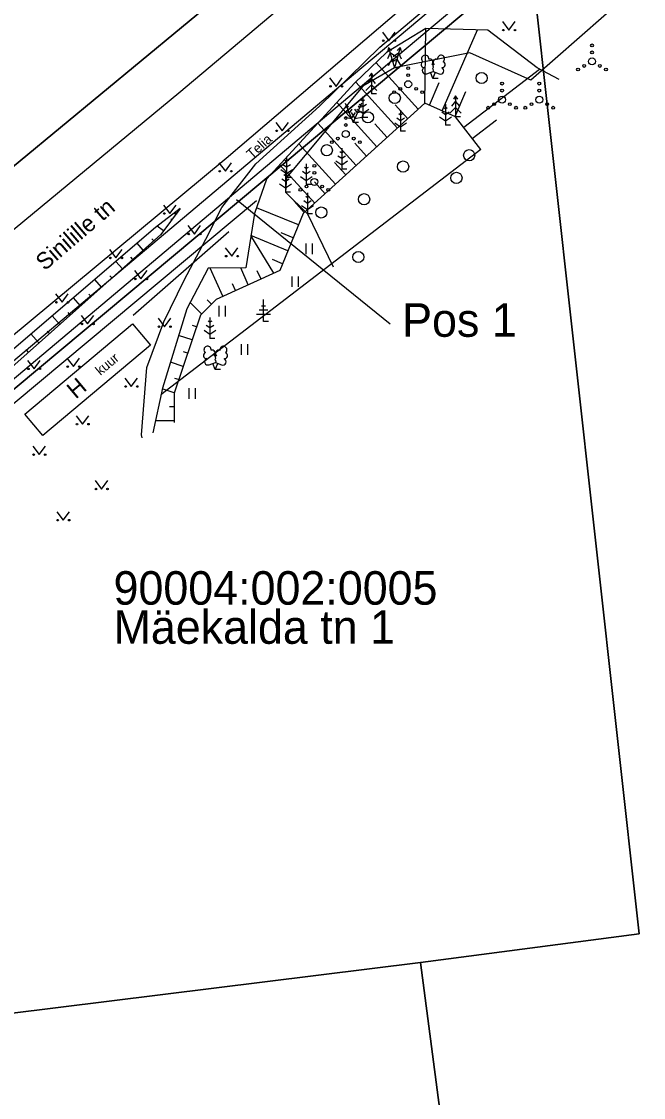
# Model space of a CAD drawing. Extents: x 648017 to 648227, y 6561313 to 6561610.
# Drawn here: x 648094.3 to 648138.8, y 6561381.6 to 6561458.6 of the extents above; entities that cross this region are included whole.
import ezdxf

# ---------------------------------------------------------------- set-up
doc = ezdxf.new("R2010")
doc.units = 0
for name, color, linetype in [('AED', 7, 'Continuous'), ('HALJASTUS', 7, 'Continuous'), ('HOONE', 7, 'Continuous'), ('KASUTUSALA', 7, 'Continuous'), ('PIIR', 7, 'Continuous'), ('PR_SIDE', 7, 'Continuous'), ('PUU', 7, 'Continuous'), ('RELJEEF', 7, 'Continuous'), ('SITRASS', 7, 'Continuous'), ('TEE', 7, 'Continuous'), ('VORMISTUS', 7, 'Continuous')]:
    doc.layers.add(name, color=color, linetype=linetype)

msp = doc.modelspace()

# ---------------------------------------------------------------- linework, layer by layer
at = {"layer": 'AED'}
msp.add_lwpolyline([(648111.122, 6561445.808), (648093.833, 6561431.357), (648080.35, 6561420.002), (648082.445, 6561407.838)], dxfattribs=at)
at = {"layer": 'HALJASTUS'}
for p, q in [((648128.734, 6561458.64), (648129.197, 6561458.033)), ((648129.197, 6561458.033), (648129.643, 6561458.64)), ((648120.134, 6561457.88), (648120.598, 6561457.274)), ((648120.598, 6561457.274), (648121.043, 6561457.88)), ((648116.354, 6561454.608), (648116.817, 6561454.001)), ((648116.817, 6561454.001), (648117.263, 6561454.608)), ((648112.504, 6561451.424), (648112.967, 6561450.818)), ((648112.967, 6561450.818), (648113.413, 6561451.424)), ((648108.424, 6561448.534), (648108.887, 6561447.928)), ((648108.887, 6561447.928), (648109.333, 6561448.534)), ((648104.45, 6561445.505), (648104.913, 6561444.899)), ((648104.913, 6561444.899), (648105.359, 6561445.505)), ((648102.276, 6561437.615), (648109.145, 6561443.615)), ((648106.203, 6561444.04), (648106.666, 6561443.433)), ((648106.666, 6561443.433), (648107.112, 6561444.04)), ((648114.639, 6561442.759), (648114.639, 6561441.998)), ((648115.094, 6561442.759), (648115.094, 6561441.998)), ((648100.589, 6561442.329), (648101.052, 6561441.722)), ((648101.052, 6561441.722), (648101.498, 6561442.329)), ((648108.88, 6561442.45), (648109.344, 6561441.844)), ((648109.344, 6561441.844), (648109.789, 6561442.45)), ((648102.377, 6561440.821), (648102.84, 6561440.214)), ((648102.84, 6561440.214), (648103.286, 6561440.821)), ((648113.649, 6561440.402), (648113.649, 6561439.641)), ((648114.104, 6561440.402), (648114.104, 6561439.641)), ((648096.727, 6561439.152), (648097.191, 6561438.545)), ((648097.191, 6561438.545), (648097.636, 6561439.152)), ((648108.423, 6561438.282), (648108.423, 6561437.521)), ((648108.878, 6561438.282), (648108.878, 6561437.521)), ((648098.551, 6561437.602), (648099.014, 6561436.995)), ((648099.014, 6561436.995), (648099.46, 6561437.602)), ((648104.07, 6561437.399), (648104.533, 6561436.792)), ((648104.533, 6561436.792), (648104.979, 6561437.399)), ((648110.027, 6561435.549), (648110.027, 6561434.788)), ((648110.482, 6561435.549), (648110.482, 6561434.788)), ((648094.725, 6561434.383), (648095.189, 6561433.776)), ((648095.189, 6561433.776), (648095.634, 6561434.383)), ((648097.537, 6561434.547), (648098, 6561433.94)), ((648098, 6561433.94), (648098.446, 6561434.547)), ((648101.683, 6561433.12), (648102.146, 6561432.513)), ((648102.146, 6561432.513), (648102.592, 6561433.12)), ((648106.265, 6561432.399), (648106.265, 6561431.638)), ((648106.72, 6561432.399), (648106.72, 6561431.638)), ((648098.193, 6561430.423), (648098.656, 6561429.816)), ((648098.656, 6561429.816), (648099.102, 6561430.423)), ((648095.088, 6561428.244), (648095.552, 6561427.637)), ((648095.552, 6561427.637), (648095.997, 6561428.244)), ((648099.555, 6561425.778), (648100.019, 6561425.172)), ((648100.019, 6561425.172), (648100.464, 6561425.778)), ((648096.809, 6561423.55), (648097.273, 6561422.943)), ((648097.273, 6561422.943), (648097.718, 6561423.55))]:
    msp.add_line(p, q, dxfattribs=at)
msp.add_lwpolyline([(648185.624, 6561501.029), (648186.158, 6561502.545), (648178.048, 6561502.668), (648168.965, 6561497.048), (648166.518, 6561494.366), (648160.96, 6561490.067), (648158.695, 6561487.313), (648156.134, 6561485.11), (648153.031, 6561483.538), (648142.942, 6561474.365), (648140.838, 6561468.512), (648139.267, 6561465.252), (648137.737, 6561460.573), (648130.77, 6561454.441), (648126.403, 6561456.396), (648120.992, 6561455.337), (648118.741, 6561454.027), (648113.276, 6561447.469), (648113.195, 6561446.44), (648114.768, 6561444.874), (648116.607, 6561441.073)], dxfattribs=at)
for centre, radius in [((648128.796, 6561458.033), 0.055), ((648129.625, 6561458.033), 0.055), ((648120.197, 6561457.274), 0.055), ((648121.025, 6561457.274), 0.055), ((648135.147, 6561456.939), 0.1), ((648135.147, 6561456.439), 0.1), ((648135.147, 6561455.789), 0.25), ((648121.982, 6561455.31), 0.1), ((648121.982, 6561454.81), 0.1), ((648127.24, 6561454.601), 0.4), ((648134.147, 6561455.214), 0.1), ((648134.582, 6561455.464), 0.1), ((648135.712, 6561455.464), 0.1), ((648136.147, 6561455.214), 0.1), ((648121.982, 6561454.16), 0.25), ((648128.703, 6561454.201), 0.1), ((648131.371, 6561454.201), 0.1), ((648116.416, 6561454.001), 0.055), ((648117.245, 6561454.001), 0.055), ((648121.023, 6561453.174), 0.4), ((648120.982, 6561453.585), 0.1), ((648121.417, 6561453.835), 0.1), ((648122.547, 6561453.835), 0.1), ((648122.982, 6561453.585), 0.1), ((648128.703, 6561453.701), 0.1), ((648131.371, 6561453.701), 0.1), ((648128.138, 6561452.726), 0.1), ((648128.703, 6561453.051), 0.25), ((648129.268, 6561452.726), 0.1), ((648130.806, 6561452.726), 0.1), ((648131.371, 6561453.051), 0.25), ((648131.936, 6561452.726), 0.1), ((648117.513, 6561451.739), 0.1), ((648119.096, 6561451.786), 0.4), ((648127.703, 6561452.476), 0.1), ((648129.703, 6561452.476), 0.1), ((648130.371, 6561452.476), 0.1), ((648132.371, 6561452.476), 0.1), ((648117.513, 6561451.239), 0.1), ((648112.566, 6561450.818), 0.055), ((648113.395, 6561450.818), 0.055), ((648116.948, 6561450.264), 0.1), ((648117.513, 6561450.589), 0.25), ((648118.078, 6561450.264), 0.1), ((648116.154, 6561449.431), 0.4), ((648116.513, 6561450.014), 0.1), ((648118.513, 6561450.014), 0.1), ((648126.349, 6561449.074), 0.4), ((648108.486, 6561447.928), 0.055), ((648109.315, 6561447.928), 0.055), ((648115.261, 6561448.315), 0.1), ((648121.617, 6561448.262), 0.4), ((648115.261, 6561447.165), 0.25), ((648115.261, 6561447.815), 0.1), ((648125.438, 6561447.45), 0.4), ((648114.261, 6561446.59), 0.1), ((648114.696, 6561446.84), 0.1), ((648115.826, 6561446.84), 0.1), ((648116.261, 6561446.59), 0.1), ((648118.826, 6561445.924), 0.4), ((648104.512, 6561444.899), 0.055), ((648105.341, 6561444.899), 0.055), ((648115.758, 6561444.974), 0.4), ((648106.265, 6561443.433), 0.055), ((648107.094, 6561443.433), 0.055), ((648108.943, 6561441.844), 0.055), ((648109.771, 6561441.844), 0.055), ((648118.41, 6561441.784), 0.4), ((648100.651, 6561441.722), 0.055), ((648101.48, 6561441.722), 0.055), ((648102.439, 6561440.214), 0.055), ((648103.268, 6561440.214), 0.055), ((648096.79, 6561438.545), 0.055), ((648097.619, 6561438.545), 0.055), ((648098.613, 6561436.995), 0.055), ((648099.442, 6561436.995), 0.055), ((648104.132, 6561436.792), 0.055), ((648104.961, 6561436.792), 0.055), ((648094.788, 6561433.776), 0.055), ((648095.616, 6561433.776), 0.055), ((648097.599, 6561433.94), 0.055), ((648098.428, 6561433.94), 0.055), ((648101.745, 6561432.513), 0.055), ((648102.574, 6561432.513), 0.055), ((648098.255, 6561429.816), 0.055), ((648099.084, 6561429.816), 0.055), ((648095.151, 6561427.637), 0.055), ((648095.98, 6561427.637), 0.055), ((648099.618, 6561425.172), 0.055), ((648100.447, 6561425.172), 0.055), ((648096.872, 6561422.943), 0.055), ((648097.701, 6561422.943), 0.055)]:
    msp.add_circle(centre, radius, dxfattribs=at)
at = {"layer": 'HOONE'}
msp.add_lwpolyline([(648094.535, 6561430.53), (648102.242, 6561436.998), (648103.52, 6561435.476), (648095.813, 6561429.007)], close=True, dxfattribs=at)
at = {"layer": 'KASUTUSALA'}
msp.add_lwpolyline([(648069.33, 6561411.95), (648079.41, 6561420.36), (648130.76, 6561463.29), (648148.46, 6561478.24), (648152.687, 6561481.861), (648163.17, 6561490.84), (648165.149, 6561492.835), (648178.343, 6561506.54), (648179.793, 6561507.812), (648180.15, 6561508.27), (648181.07, 6561509.57), (648179.717, 6561510.405), (648176.961, 6561507.989), (648163.749, 6561494.265), (648163.1, 6561493.666), (648154.204, 6561485.901), (648141.111, 6561474.192), (648118.068, 6561454.823), (648078.72, 6561421.738), (648068.502, 6561412.945), (648066.261, 6561409.593)], close=True, dxfattribs=at)
at = {"layer": 'PIIR'}
for points in [[(648199.342, 6561559.885), (648199.07, 6561558.2), (648195.16, 6561543.45), (648190.37, 6561530.46), (648184.89, 6561519.28), (648179.37, 6561510.62), (648181.07, 6561509.57), (648180.15, 6561508.27), (648175.42, 6561502.2), (648170.88, 6561497.65), (648163.17, 6561490.84), (648148.46, 6561478.24), (648130.76, 6561463.29), (648079.41, 6561420.36), (648069.33, 6561411.95), (648039.275, 6561388.867)], [(648148.783, 6561559.885), (648090, 6561513.15), (648123.09, 6561472.56), (648039.275, 6561403.329)], [(648039.275, 6561403.329), (648123.09, 6561472.56), (648162.4, 6561506.57), (648170.84, 6561515.84), (648172.53, 6561514.72), (648177.65, 6561522.71), (648182.83, 6561533.2), (648187.47, 6561545.71), (648191.21, 6561559.62), (648191.239, 6561559.885)], [(648128.277, 6561349.885), (648122.86, 6561391.28), (648138.52, 6561393.32), (648130.76, 6561463.29), (648148.46, 6561478.24), (648163.17, 6561490.84), (648170.88, 6561497.65), (648175.42, 6561502.2), (648180.15, 6561508.27), (648181.07, 6561509.57), (648185.28, 6561507.91), (648190.43, 6561507.33), (648190.49, 6561494.61), (648191.59, 6561478.79), (648183.88, 6561478.99), (648183.75, 6561472.33), (648192.14, 6561472), (648192.72, 6561465.96), (648194.12, 6561456.75), (648195.36, 6561449.36), (648197.34, 6561442.54), (648200.74, 6561433.7), (648204.275, 6561426.345)], [(648090.928, 6561349.885), (648085.73, 6561386.66), (648122.86, 6561391.28), (648128.277, 6561349.885)]]:
    msp.add_lwpolyline(points, dxfattribs=at)
msp.add_lwpolyline([(648079.41, 6561420.36), (648130.76, 6561463.29), (648138.52, 6561393.32), (648122.86, 6561391.28), (648085.73, 6561386.66)], close=True, dxfattribs=at)
at = {"layer": 'PR_SIDE'}
msp.add_lwpolyline([(648199.292, 6561518.475), (648197.479, 6561519.53), (648193.724, 6561520.506), (648191.997, 6561519.841), (648177.652, 6561507.265), (648164.449, 6561493.55), (648163.768, 6561492.922), (648154.867, 6561485.151), (648141.766, 6561473.436), (648118.712, 6561454.058), (648079.383, 6561420.989), (648069.186, 6561412.213), (648060.526, 6561403.421), (648044.656, 6561390.621), (648039.275, 6561386.529)], dxfattribs=at)
at = {"layer": 'PUU'}
for p, q in [((648120.583, 6561456.781), (648120.507, 6561456.499)), ((648120.795, 6561456.581), (648120.583, 6561456.781)), ((648120.583, 6561456.781), (648120.992, 6561455.337)), ((648121.401, 6561456.781), (648120.992, 6561455.337)), ((648121.188, 6561456.581), (648121.401, 6561456.781)), ((648121.401, 6561456.781), (648121.477, 6561456.499)), ((648120.692, 6561456.396), (648120.499, 6561455.977)), ((648120.815, 6561455.963), (648120.539, 6561455.469)), ((648121.076, 6561456.141), (648120.692, 6561456.396)), ((648121.076, 6561455.817), (648120.815, 6561455.963)), ((648120.908, 6561456.141), (648121.292, 6561456.396)), ((648120.908, 6561455.817), (648121.169, 6561455.963)), ((648121.169, 6561455.963), (648121.445, 6561455.469)), ((648121.292, 6561456.396), (648121.485, 6561455.977)), ((648119.346, 6561454.958), (648119.196, 6561454.708)), ((648119.496, 6561454.708), (648119.346, 6561454.958)), ((648119.346, 6561454.958), (648119.346, 6561453.458)), ((648121.352, 6561455.337), (648120.992, 6561455.337)), ((648123.315, 6561454.905), (648123.76, 6561455.08)), ((648123.755, 6561454.57), (648123.58, 6561455.01)), ((648123.755, 6561454.57), (648123.935, 6561455.01)), ((648123.76, 6561455.08), (648124.2, 6561454.9)), ((648119.346, 6561454.558), (648119.046, 6561454.208)), ((648119.646, 6561454.208), (648119.346, 6561454.558)), ((648124.135, 6561454.57), (648123.755, 6561454.57)), ((648119.346, 6561454.108), (648118.946, 6561453.708)), ((648119.746, 6561453.708), (648119.346, 6561454.108)), ((648119.706, 6561453.458), (648119.346, 6561453.458)), ((648117.469, 6561452.805), (648118.052, 6561451.423)), ((648117.688, 6561452.608), (648117.605, 6561452.483)), ((648118.634, 6561452.805), (648118.052, 6561451.423)), ((648118.498, 6561452.483), (648118.416, 6561452.608)), ((648118.736, 6561452.536), (648118.469, 6561452.714)), ((648118.736, 6561452.936), (648118.611, 6561453.019)), ((648118.736, 6561453.286), (648118.736, 6561451.786)), ((648118.86, 6561453.019), (648118.736, 6561452.936)), ((648119.002, 6561452.714), (648118.736, 6561452.536)), ((648124.647, 6561452.724), (648124.647, 6561451.224)), ((648125.376, 6561452.934), (648125.076, 6561452.584)), ((648125.376, 6561453.334), (648125.226, 6561453.084)), ((648125.526, 6561453.084), (648125.376, 6561453.334)), ((648125.376, 6561453.334), (648125.376, 6561451.834)), ((648125.676, 6561452.584), (648125.376, 6561452.934)), ((648117.76, 6561452.114), (648117.446, 6561452.175)), ((648117.605, 6561452.483), (648117.458, 6561452.511)), ((648117.937, 6561452.382), (648117.76, 6561452.114)), ((648117.889, 6561452.131), (648118.171, 6561451.706)), ((648117.933, 6561451.706), (648118.214, 6561452.131)), ((648118.343, 6561452.114), (648118.166, 6561452.382)), ((648118.312, 6561452.375), (648118.736, 6561452.093)), ((648118.657, 6561452.175), (648118.343, 6561452.114)), ((648118.645, 6561452.511), (648118.498, 6561452.483)), ((648118.736, 6561452.093), (648119.16, 6561452.375)), ((648121.44, 6561451.943), (648121.315, 6561452.026)), ((648121.44, 6561452.293), (648121.44, 6561450.793)), ((648121.564, 6561452.026), (648121.44, 6561451.943)), ((648124.223, 6561451.814), (648124.647, 6561451.531)), ((648124.647, 6561451.974), (648124.381, 6561452.152)), ((648124.647, 6561452.374), (648124.523, 6561452.457)), ((648124.772, 6561452.457), (648124.647, 6561452.374)), ((648124.914, 6561452.152), (648124.647, 6561451.974)), ((648124.647, 6561451.531), (648125.072, 6561451.814)), ((648125.376, 6561452.484), (648124.976, 6561452.084)), ((648125.776, 6561452.084), (648125.376, 6561452.484)), ((648125.736, 6561451.834), (648125.376, 6561451.834)), ((648117.432, 6561451.802), (648117.933, 6561451.706)), ((648118.412, 6561451.423), (648118.052, 6561451.423)), ((648118.171, 6561451.706), (648118.671, 6561451.802)), ((648119.096, 6561451.786), (648118.736, 6561451.786)), ((648121.015, 6561451.382), (648121.44, 6561451.099)), ((648121.44, 6561451.543), (648121.173, 6561451.721)), ((648121.706, 6561451.721), (648121.44, 6561451.543)), ((648121.44, 6561451.099), (648121.864, 6561451.382)), ((648125.007, 6561451.224), (648124.647, 6561451.224)), ((648121.8, 6561450.793), (648121.44, 6561450.793)), ((648117.22, 6561449.583), (648117.22, 6561448.083)), ((648113.276, 6561448.969), (648113.276, 6561447.469)), ((648117.22, 6561448.833), (648116.953, 6561449.01)), ((648117.22, 6561449.233), (648117.095, 6561449.316)), ((648117.344, 6561449.316), (648117.22, 6561449.233)), ((648117.486, 6561449.01), (648117.22, 6561448.833)), ((648112.852, 6561448.059), (648113.276, 6561447.776)), ((648113.276, 6561448.219), (648113.009, 6561448.397)), ((648113.276, 6561448.619), (648113.152, 6561448.702)), ((648113.401, 6561448.702), (648113.276, 6561448.619)), ((648113.543, 6561448.397), (648113.276, 6561448.219)), ((648113.276, 6561447.776), (648113.7, 6561448.059)), ((648114.685, 6561448.119), (648114.56, 6561448.202)), ((648114.685, 6561448.469), (648114.685, 6561446.969)), ((648114.809, 6561448.202), (648114.685, 6561448.119)), ((648116.795, 6561448.672), (648117.22, 6561448.389)), ((648117.22, 6561448.389), (648117.644, 6561448.672)), ((648117.58, 6561448.083), (648117.22, 6561448.083)), ((648113.195, 6561447.19), (648112.929, 6561447.368)), ((648113.195, 6561447.59), (648113.071, 6561447.673)), ((648113.195, 6561447.94), (648113.195, 6561446.44)), ((648113.32, 6561447.673), (648113.195, 6561447.59)), ((648113.462, 6561447.368), (648113.195, 6561447.19)), ((648113.636, 6561447.469), (648113.276, 6561447.469)), ((648114.26, 6561447.559), (648114.685, 6561447.276)), ((648114.685, 6561447.719), (648114.418, 6561447.897)), ((648114.951, 6561447.897), (648114.685, 6561447.719)), ((648114.685, 6561447.276), (648115.109, 6561447.559)), ((648112.771, 6561447.029), (648113.195, 6561446.747)), ((648113.195, 6561446.747), (648113.62, 6561447.029)), ((648113.555, 6561446.44), (648113.195, 6561446.44)), ((648115.045, 6561446.969), (648114.685, 6561446.969)), ((648114.768, 6561445.624), (648114.501, 6561445.801)), ((648114.768, 6561446.024), (648114.643, 6561446.107)), ((648114.768, 6561446.374), (648114.768, 6561444.874)), ((648114.892, 6561446.107), (648114.768, 6561446.024)), ((648115.034, 6561445.801), (648114.768, 6561445.624)), ((648114.343, 6561445.463), (648114.768, 6561445.18)), ((648114.768, 6561445.18), (648115.192, 6561445.463)), ((648115.128, 6561444.874), (648114.768, 6561444.874)), ((648111.62, 6561437.172), (648111.62, 6561438.747)), ((648111.92, 6561437.972), (648111.32, 6561437.972)), ((648111.77, 6561438.272), (648111.47, 6561438.272)), ((648107.783, 6561437.112), (648107.659, 6561437.195)), ((648107.783, 6561437.462), (648107.783, 6561435.962)), ((648107.908, 6561437.195), (648107.783, 6561437.112)), ((648112.12, 6561437.672), (648111.12, 6561437.672)), ((648111.98, 6561437.172), (648111.62, 6561437.172)), ((648107.359, 6561436.552), (648107.783, 6561436.269)), ((648107.783, 6561436.712), (648107.517, 6561436.89)), ((648108.05, 6561436.89), (648107.783, 6561436.712)), ((648107.783, 6561436.269), (648108.208, 6561436.552)), ((648108.143, 6561435.962), (648107.783, 6561435.962)), ((648107.729, 6561434.067), (648108.174, 6561434.242)), ((648108.169, 6561433.732), (648107.994, 6561434.173)), ((648108.169, 6561433.732), (648108.349, 6561434.173)), ((648108.174, 6561434.242), (648108.614, 6561434.062)), ((648108.549, 6561433.732), (648108.169, 6561433.732))]:
    msp.add_line(p, q, dxfattribs=at)
for points in [[(648123.76, 6561455.575), (648123.74, 6561455.5), (648123.74, 6561455.48), (648123.75, 6561455.45), (648123.77, 6561455.415), (648123.775, 6561455.395), (648123.76, 6561455.36), (648123.735, 6561455.31), (648123.73, 6561455.285), (648123.735, 6561455.27), (648123.745, 6561455.24), (648123.78, 6561455.18), (648123.785, 6561455.16), (648123.78, 6561455.14), (648123.765, 6561455.105), (648123.76, 6561455.08)], [(648108.174, 6561434.737), (648108.154, 6561434.663), (648108.154, 6561434.643), (648108.164, 6561434.612), (648108.184, 6561434.578), (648108.189, 6561434.558), (648108.174, 6561434.522), (648108.149, 6561434.473), (648108.144, 6561434.447), (648108.149, 6561434.433), (648108.159, 6561434.402), (648108.194, 6561434.343), (648108.199, 6561434.322), (648108.194, 6561434.303), (648108.179, 6561434.268), (648108.174, 6561434.242)]]:
    msp.add_lwpolyline(points, dxfattribs=at)
for centre, radius, start, end in [((648123.124, 6561455.573), 0.224, 111.43041, 274.49868), ((648123.198, 6561455.985), 0.256, 111.50269, 232.51731), ((648123.198, 6561455.985), 0.256, 350.48556, 111.50017), ((648123.532, 6561455.734), 0.224, 308.50412, 111.57247), ((648123.996, 6561455.729), 0.225, 67.7016, 230.51262), ((648124.334, 6561455.976), 0.256, 67.6168, 188.63142), ((648124.401, 6561455.563), 0.224, 264.6183, 67.68657), ((648124.334, 6561455.976), 0.256, 306.59966, 67.61428), ((648123.229, 6561455.129), 0.237, 111.50143, 291.50036), ((648123.759, 6561455.338), 0.237, 66.76552, 111.50149), ((648124.29, 6561455.121), 0.237, 247.61661, 67.61554), ((648107.538, 6561434.735), 0.224, 111.43041, 274.49868), ((648107.611, 6561435.147), 0.256, 111.50269, 232.51731), ((648107.611, 6561435.147), 0.256, 350.48556, 111.50017), ((648107.946, 6561434.896), 0.224, 308.50412, 111.57247), ((648108.409, 6561434.892), 0.225, 67.7016, 230.51262), ((648108.747, 6561435.138), 0.256, 67.6168, 188.63142), ((648108.815, 6561434.725), 0.224, 264.6183, 67.68657), ((648108.747, 6561435.138), 0.256, 306.59966, 67.61428), ((648107.642, 6561434.291), 0.237, 111.50143, 291.50036), ((648108.173, 6561434.5), 0.237, 66.76552, 111.50149), ((648108.703, 6561434.283), 0.237, 247.61661, 67.61554)]:
    msp.add_arc(centre, radius, start, end, dxfattribs=at)
at = {"layer": 'RELJEEF'}
for p, q in [((648123.173, 6561452.79), (648123.256, 6561458.146)), ((648124.42, 6561452.249), (648126.936, 6561458.047)), ((648122.698, 6561452.361), (648119.673, 6561455.702)), ((648125.959, 6561451.074), (648131.391, 6561455.244)), ((648121.215, 6561451.018), (648118.229, 6561454.317)), ((648123.503, 6561452.647), (648124.209, 6561454.276)), ((648125.337, 6561451.851), (648126.117, 6561453.647)), ((648119.733, 6561449.676), (648116.868, 6561452.84)), ((648121.957, 6561451.689), (648121.055, 6561452.685)), ((648118.25, 6561448.334), (648115.511, 6561451.359)), ((648120.474, 6561450.347), (648119.596, 6561451.317)), ((648126.568, 6561450.281), (648128.307, 6561451.615)), ((648116.767, 6561446.991), (648114.154, 6561449.878)), ((648118.991, 6561449.005), (648118.151, 6561449.933)), ((648127.177, 6561449.488), (648104.275, 6561431.908)), ((648115.285, 6561445.649), (648112.797, 6561448.397)), ((648117.509, 6561447.663), (648116.706, 6561448.549)), ((648116.026, 6561446.32), (648115.261, 6561447.165)), ((648114.543, 6561444.978), (648113.816, 6561445.781)), ((648114.119, 6561444.085), (648111.112, 6561445.317)), ((648105.057, 6561444.449), (648104.989, 6561444.5)), ((648104.457, 6561443.649), (648104.008, 6561443.986)), ((648113.74, 6561443.159), (648112.88, 6561443.511)), ((648103.008, 6561442.278), (648102.571, 6561442.77)), ((648103.756, 6561442.942), (648103.628, 6561443.085)), ((648113.361, 6561442.234), (648110.717, 6561443.317)), ((648112.352, 6561440.624), (648110.717, 6561443.317)), ((648101.514, 6561440.949), (648101.05, 6561441.471)), ((648102.261, 6561441.613), (648102.126, 6561441.765)), ((648112.981, 6561441.308), (648112.255, 6561441.606)), ((648100.766, 6561440.284), (648100.623, 6561440.446)), ((648108.709, 6561438.972), (648107.796, 6561440.986)), ((648110.531, 6561439.798), (648109.984, 6561441.003)), ((648111.442, 6561440.211), (648111.172, 6561440.806)), ((648100.019, 6561439.62), (648099.528, 6561440.172)), ((648109.62, 6561439.385), (648109.401, 6561439.868)), ((648098.524, 6561438.291), (648098.007, 6561438.873)), ((648099.272, 6561438.956), (648099.12, 6561439.126)), ((648107.895, 6561438.421), (648107.583, 6561438.731)), ((648107.189, 6561437.712), (648106.369, 6561438.529)), ((648097.03, 6561436.962), (648096.486, 6561437.574)), ((648097.777, 6561437.627), (648097.618, 6561437.806)), ((648096.282, 6561436.298), (648096.115, 6561436.486)), ((648106.822, 6561436.793), (648106.527, 6561436.894)), ((648095.535, 6561435.633), (648094.965, 6561436.275)), ((648106.502, 6561435.846), (648105.542, 6561436.171)), ((648094.787, 6561434.969), (648094.612, 6561435.166)), ((648106.181, 6561434.899), (648105.9, 6561434.994)), ((648105.86, 6561433.952), (648104.952, 6561434.259)), ((648105.539, 6561433.005), (648105.274, 6561433.094)), ((648105.218, 6561432.058), (648104.368, 6561432.346)), ((648105.217, 6561431.059), (648104.88, 6561431.057)), ((648105.221, 6561430.059), (648103.884, 6561430.053))]:
    msp.add_line(p, q, dxfattribs=at)
for points in [[(648132.785, 6561454.505), (648131.221, 6561455.333), (648127.685, 6561458.027), (648123.256, 6561458.146), (648120.438, 6561456.437), (648118.162, 6561454.252), (648111.845, 6561447.357), (648110.964, 6561444.906), (648110.358, 6561441.006), (648107.666, 6561440.985), (648106.126, 6561438.068), (648104.378, 6561432.395), (648103.704, 6561429.2)], [(648127.177, 6561449.488), (648125.376, 6561451.834), (648123.173, 6561452.79), (648114.45, 6561444.894), (648112.781, 6561440.819), (648108.224, 6561438.752), (648107.105, 6561437.628), (648105.213, 6561432.042), (648105.222, 6561429.946)], [(648105.657, 6561445.249), (648104.268, 6561443.398), (648092.722, 6561433.133), (648081.823, 6561423.43), (648080.08, 6561420.264), (648079.06, 6561417.48)], [(648105.657, 6561445.249), (648103.887, 6561443.894), (648092.031, 6561433.769), (648081.397, 6561423.96), (648079.154, 6561420.435), (648079.06, 6561417.48)]]:
    msp.add_lwpolyline(points, dxfattribs=at)
at = {"layer": 'SITRASS'}
msp.add_lwpolyline([(648102.922, 6561428.846), (648102.88, 6561429.06), (648103.27, 6561433.88), (648104.47, 6561437.15), (648105.93, 6561440.13), (648107.48, 6561443.06), (648108.63, 6561445.32), (648111.07, 6561448.46), (648115.64, 6561452.59), (648119.94, 6561456.82), (648127.38, 6561463.08), (648135.65, 6561470.85), (648142, 6561476.76)], dxfattribs=at)
at = {"layer": 'TEE'}
for points in [[(648190.847, 6561503.014), (648190.795, 6561505.329), (648190.473, 6561508.69), (648186.913, 6561508.391), (648184.052, 6561507.669), (648178.235, 6561505.797), (648172.597, 6561503.638), (648169.601, 6561500.659), (648161.13, 6561493.277), (648153.241, 6561486.387), (648142.295, 6561477.024), (648134.213, 6561470.18), (648127.303, 6561464.531), (648121.652, 6561459.668), (648108.949, 6561448.834), (648091.715, 6561434.542), (648078.474, 6561423.42), (648076.859, 6561419.217), (648076.802, 6561415.34), (648077.814, 6561412.283), (648079.886, 6561408.026), (648080.807, 6561407.116)], [(648123.326, 6561469.198), (648122.878, 6561468.198), (648118.137, 6561464.111), (648105.565, 6561453.509), (648088.284, 6561439.263), (648074.857, 6561428.431), (648059.756, 6561415.877), (648040.748, 6561400.235), (648039.275, 6561399.135)]]:
    msp.add_lwpolyline(points, dxfattribs=at)
at = {"layer": 'VORMISTUS'}
msp.add_line((648109.679, 6561445.913), (648120.689, 6561437.011), dxfattribs=at)

# ---------------------------------------------------------------- texts
at = {"layer": 'HOONE'}
for s, height, p in [('kuur', 0.7, (648099.94, 6561433.269)), ('H', 1.2, (648098.169, 6561431.573))]:
    msp.add_text(s, height=height, rotation=40.00738, dxfattribs=at).set_placement(p)
at = {"layer": 'PIIR'}
for s, p in [('90004:002:0005', (648100.878, 6561416.892)), ('Mäekalda tn 1', (648100.878, 6561414.092))]:
    msp.add_text(s, height=2.4, dxfattribs=at).set_placement(p)
at = {"layer": 'SITRASS'}
msp.add_text('Telia', height=0.7, rotation=42.05912, dxfattribs=at).set_placement((648110.789, 6561448.772))
at = {"layer": 'TEE'}
msp.add_text('Sinilille tn', height=1.2, rotation=40.72363, dxfattribs=at).set_placement((648095.952, 6561440.755))
at = {"layer": 'VORMISTUS'}
msp.add_text('Pos 1', height=2.4, dxfattribs=at).set_placement((648121.549, 6561436.074))

doc.saveas('drawing.dxf')
